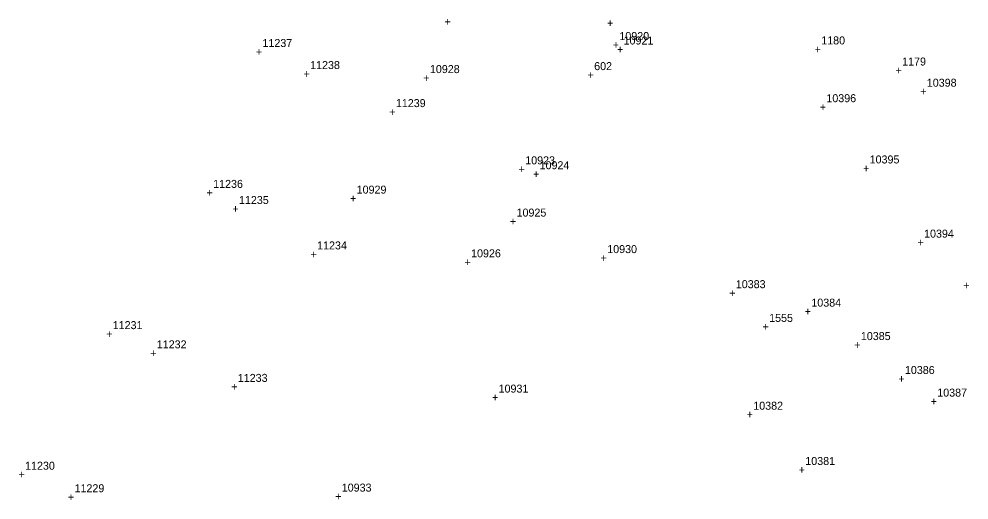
# Model space of a CAD drawing. Extents: x 1160051 to 1162814, y 614604 to 619560.
# Drawn here: x 1160998 to 1161294.7, y 617088.6 to 617238.9 of the extents above; entities that cross this region are included whole.
import ezdxf

# ---------------------------------------------------------------- set-up
doc = ezdxf.new("R2010")
doc.units = 0
for name, color, linetype in [('S_Control_Temp_Traverse', 7, 'Continuous'), ('S_Ground_Elevation', 7, 'Continuous'), ('S_Guardrail_Beam', 7, 'Continuous'), ('S_Trees_TreeLine', 7, 'Continuous'), ('S_Utilities_UG_BoringLocation', 7, 'Continuous')]:
    doc.layers.add(name, color=color, linetype=linetype)

msp = doc.modelspace()

# ---------------------------------------------------------------- texts
at = {"layer": 'S_Control_Temp_Traverse'}
for s, p in [('602', (1161177.62, 617222.96)), ('602', (1161177.62, 617222.96)), ('602', (1161177.62, 617222.96)), ('+', (1161175.56, 617220.21)), ('+', (1161175.56, 617220.21)), ('+', (1161175.56, 617220.21))]:
    msp.add_text(s, height=2.5, dxfattribs=at).set_placement(p)
at = {"layer": 'S_Ground_Elevation'}
for s, p in [('+', (1161130.91, 617236.84)), ('11237', (1161074.04, 617230.18)), ('10920', (1161185.49, 617232.36)), ('1180', (1161248.53, 617230.99)), ('+', (1161071.98, 617227.43)), ('+', (1161183.43, 617229.61)), ('+', (1161246.47, 617228.24)), ('1179', (1161273.79, 617224.4)), ('11238', (1161088.93, 617223.29)), ('+', (1161271.73, 617221.66)), ('+', (1161086.87, 617220.54)), ('10398', (1161281.49, 617217.77)), ('10396', (1161250.13, 617212.93)), ('+', (1161279.43, 617215.02)), ('11239', (1161115.7, 617211.4)), ('+', (1161248.07, 617210.18)), ('+', (1161113.64, 617208.65)), ('10924', (1161160.58, 617191.98)), ('10395', (1161263.64, 617193.79)), ('+', (1161158.52, 617189.23)), ('+', (1161261.58, 617191.04)), ('11236', (1161058.65, 617186.15)), ('+', (1161056.59, 617183.4)), ('11235', (1161066.71, 617181.11)), ('+', (1161064.65, 617178.36)), ('10925', (1161153.39, 617177.18)), ('+', (1161151.33, 617174.43)), ('10394', (1161280.64, 617170.6)), ('+', (1161278.58, 617167.85)), ('11234', (1161091.11, 617166.92)), ('10930', (1161181.7, 617165.77)), ('+', (1161089.05, 617164.17)), ('+', (1161179.64, 617163.02)), ('10383', (1161221.85, 617154.81)), ('+', (1161292.88, 617154.39)), ('+', (1161219.79, 617152.06)), ('10384', (1161245.44, 617149.04)), ('+', (1161243.38, 617146.29)), ('11231', (1161027.28, 617142.01)), ('+', (1161025.22, 617139.26)), ('10385', (1161260.9, 617138.59)), ('11232', (1161041.04, 617136)), ('+', (1161258.84, 617135.84)), ('+', (1161038.98, 617133.25)), ('10386', (1161274.66, 617127.98)), ('11233', (1161066.34, 617125.52)), ('+', (1161272.6, 617125.23)), ('+', (1161064.27, 617122.77)), ('10931', (1161147.78, 617122.17)), ('10387', (1161284.76, 617120.92)), ('+', (1161145.72, 617119.42)), ('+', (1161282.7, 617118.17)), ('10382', (1161227.3, 617116.82)), ('+', (1161225.24, 617114.08)), ('10381', (1161243.55, 617099.55)), ('11230', (1160999.92, 617098.07)), ('+', (1161241.49, 617096.8)), ('+', (1160997.85, 617095.32)), ('11229', (1161015.36, 617091.03)), ('10933', (1161098.8, 617091.23)), ('+', (1161013.3, 617088.28)), ('+', (1161096.74, 617088.48))]:
    msp.add_text(s, height=2.5, dxfattribs=at).set_placement(p)
at = {"layer": 'S_Guardrail_Beam'}
for s, p in [('+', (1161181.65, 617236.43)), ('10928', (1161126.33, 617222.03)), ('+', (1161124.26, 617219.28)), ('10923', (1161156.09, 617193.51)), ('+', (1161154.03, 617190.76)), ('10929', (1161103.46, 617184.36)), ('+', (1161101.4, 617181.61)), ('10926', (1161139.19, 617164.45)), ('+', (1161137.13, 617161.7))]:
    msp.add_text(s, height=2.5, dxfattribs=at).set_placement(p)
at = {"layer": 'S_Trees_TreeLine'}
for s, p in [('10921', (1161186.81, 617230.96)), ('+', (1161184.75, 617228.21))]:
    msp.add_text(s, height=2.5, dxfattribs=at).set_placement(p)
at = {"layer": 'S_Utilities_UG_BoringLocation'}
for s, p in [('1555', (1161232.26, 617144.26)), ('+', (1161230.2, 617141.51))]:
    msp.add_text(s, height=2.5, dxfattribs=at).set_placement(p)

doc.saveas('drawing.dxf')
